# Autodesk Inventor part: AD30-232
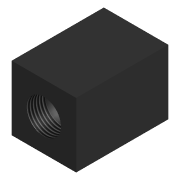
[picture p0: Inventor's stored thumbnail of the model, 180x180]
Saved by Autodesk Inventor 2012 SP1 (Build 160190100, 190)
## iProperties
Shininess: 0.0
Length Units: 11269
Angle Units: 11279
Time Units: 11290
Mass Units: 11283
Length Display Precision: 3
Angle Display Precision: 2
Compacted: True
Created: 2000-06
Part Number: AD30-232
Project: BONDING PRESS
Description: SHOCK MOUNT
Document SubType Name: Modeling
Designer: Ron
Material: Aluminum-6061-AHC
Density: 1 g/cm^3
Density: 0.0
Volumn: 0.0
Area: 0.0
PropertySet Name: Model Information
Control State: 0
Master: False
Checked Out: False
Title: SHOCK MOUNT
Author: Ron
Revision Number: A
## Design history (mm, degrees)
node "Extrusion1" dims "d2" = 63.5, "d3" = 0
  sketch "Sketch1"
    geometry: L1 (-22.225, -22.225)-(22.225, -22.225); L2 (22.225, -22.225)-(22.225, 22.225); L3 (22.225, 22.225)-(-22.225, 22.225); L4 (-22.225, 22.225)-(-22.225, -22.225); L5 (-22.225, -22.225)-(22.225, 22.225); 2 further points
    constraints: 10 end point, 2 parallel, 1 coincident, 1 horizontal, 1 midpoint, 1 perpendicular
    dimensions: "d0" = 44.45 distance of L2.end L3.end; "d1" = 44.45 distance of L1.end L2.end (= d0)
node "Hole1" dims "d4" = 23.622, "d5" = 4, "d6" = 2, "d7" = 60 deg, "d8" = 8, "d9" = 118 deg, "d21" = 6
  sketch "Sketch2"
    geometry: L1 (-22.225, -22.225)-(22.225, 22.225); 1 further point
    constraints: 2 end point, 1 midpoint
node "Extrusion2" dims "d11" = 50.8, "d12" = 0
  sketch "Sketch3"
    geometry: C1 r 11.811 at (0, 0) reference; C2 r 14.287 at (0, 0)
    constraints: 1 centre point, 1 coincident
    dimensions: "d10" = 28.575 diameter of C2
node "Hole2" dims "d14" = 3.242, "d15" = 4, "d16" = 2, "d17" = 60 deg, "d18" = 12, "d19" = 118 deg, "d20" = 8
  sketch "Sketch4"
    geometry: L1 (22.225, -22.225)-(-22.225, -22.225) reference; L2 (22.225, 22.225)-(22.225, -22.225) reference; L3 (-22.225, 22.225)-(22.225, 22.225) reference; L4 (-22.225, -22.225)-(-22.225, 22.225) reference; L5 (15.875, -15.875)-(-15.875, -15.875); L6 (-15.875, -15.875)-(-15.875, 15.875); L7 (-15.875, 15.875)-(15.875, 15.875); L8 (15.875, 15.875)-(15.875, -15.875); 4 further points
    constraints: 8 end point, 4 coincident, 3 other
    dimensions: "d13" = 31.75 distance of L6.end L7.end
workplane "Work Plane1"
body "Solid1"
